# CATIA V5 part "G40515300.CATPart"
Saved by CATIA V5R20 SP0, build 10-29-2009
Part number: G40515300
Revision: 7
Definition: design
Nomenclature: G40515300
Source: made
Description: NOT SPECIFIED
Bounding box of the stored display mesh (mm): x -150 to 150, y -10 to 10, z -15 to 0
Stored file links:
  C:\Users\Raffaele\Desktop\3D X SITO CF\BOLEX\29-GUIDE STRIP REF 405\G40515300.CATPart
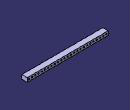
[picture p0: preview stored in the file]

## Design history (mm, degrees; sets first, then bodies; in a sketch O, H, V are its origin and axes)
Body1 "MANIFOLD_SOLID_BREP #5246" (main body)
  Solid1: solid without history
Body2 "MANIFOLD_SOLID_BREP #5384"
  Solid2: solid without history
Body3 "MANIFOLD_SOLID_BREP #5496"
  Solid3: solid without history
Body4 "MANIFOLD_SOLID_BREP #5608"
  Solid4: solid without history
Body5 "MANIFOLD_SOLID_BREP #5720"
  Solid5: solid without history
Body6 "MANIFOLD_SOLID_BREP #5832"
  Solid6: solid without history
Body7 "MANIFOLD_SOLID_BREP #5944"
  Solid7: solid without history
Body8 "MANIFOLD_SOLID_BREP #6056"
  Solid8: solid without history
Body9 "MANIFOLD_SOLID_BREP #6168"
  Solid9: solid without history
Body10 "MANIFOLD_SOLID_BREP #6280"
  Solid10: solid without history
Body11 "MANIFOLD_SOLID_BREP #6392"
  Solid11: solid without history
Body12 "MANIFOLD_SOLID_BREP #6504"
  Solid12: solid without history
Body13 "MANIFOLD_SOLID_BREP #6616"
  Solid13: solid without history
Body14 "MANIFOLD_SOLID_BREP #6728"
  Solid14: solid without history
Body15 "MANIFOLD_SOLID_BREP #6840"
  Solid15: solid without history
Body16 "MANIFOLD_SOLID_BREP #6952"
  Solid16: solid without history
Body17 "MANIFOLD_SOLID_BREP #7064"
  Solid17: solid without history
Body18 "MANIFOLD_SOLID_BREP #7176"
  Solid18: solid without history
Body19 "MANIFOLD_SOLID_BREP #7288"
  Solid19: solid without history
Body20 "MANIFOLD_SOLID_BREP #7400"
  Solid20: solid without history
Body21 "MANIFOLD_SOLID_BREP #7512"
  Solid21: solid without history
Body22 "MANIFOLD_SOLID_BREP #7624"
  Solid22: solid without history
Body23 "MANIFOLD_SOLID_BREP #7736"
  Solid23: solid without history
Body24 "MANIFOLD_SOLID_BREP #7848"
  Solid24: solid without history
Body25 "MANIFOLD_SOLID_BREP #7960"
  Solid25: solid without history
Body26 "MANIFOLD_SOLID_BREP #8072"
  Solid26: solid without history
Body27 "MANIFOLD_SOLID_BREP #8184"
  Solid27: solid without history
Body28 "MANIFOLD_SOLID_BREP #8322"
  Solid28: solid without history
Body29 "MANIFOLD_SOLID_BREP #8460"
  Solid29: solid without history
Body30 "MANIFOLD_SOLID_BREP #8598"
  Solid30: solid without history
Body31 "MANIFOLD_SOLID_BREP #8736"
  Solid31: solid without history
Body32 "MANIFOLD_SOLID_BREP #8874"
  Solid32: solid without history
Body33 "MANIFOLD_SOLID_BREP #9012"
  Solid33: solid without history
Body34 "MANIFOLD_SOLID_BREP #9150"
  Solid34: solid without history
Body35 "MANIFOLD_SOLID_BREP #9288"
  Solid35: solid without history
Body36 "MANIFOLD_SOLID_BREP #9426"
  Solid36: solid without history
Body37 "MANIFOLD_SOLID_BREP #9564"
  Solid37: solid without history
Body38 "MANIFOLD_SOLID_BREP #9702"
  Solid38: solid without history
Body39 "MANIFOLD_SOLID_BREP #9840"
  Solid39: solid without history
Body40 "MANIFOLD_SOLID_BREP #9978"
  Solid40: solid without history
Body41 "MANIFOLD_SOLID_BREP #10116"
  Solid41: solid without history
Body42 "MANIFOLD_SOLID_BREP #10254"
  Solid42: solid without history
Body43 "MANIFOLD_SOLID_BREP #10392"
  Solid43: solid without history
Body44 "MANIFOLD_SOLID_BREP #10530"
  Solid44: solid without history
Body45 "MANIFOLD_SOLID_BREP #10668"
  Solid45: solid without history
Body46 "MANIFOLD_SOLID_BREP #10806"
  Solid46: solid without history
Body47 "MANIFOLD_SOLID_BREP #10944"
  Solid47: solid without history
Body48 "MANIFOLD_SOLID_BREP #11082"
  Solid48: solid without history
Body49 "MANIFOLD_SOLID_BREP #11220"
  Solid49: solid without history
Body50 "MANIFOLD_SOLID_BREP #11358"
  Solid50: solid without history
